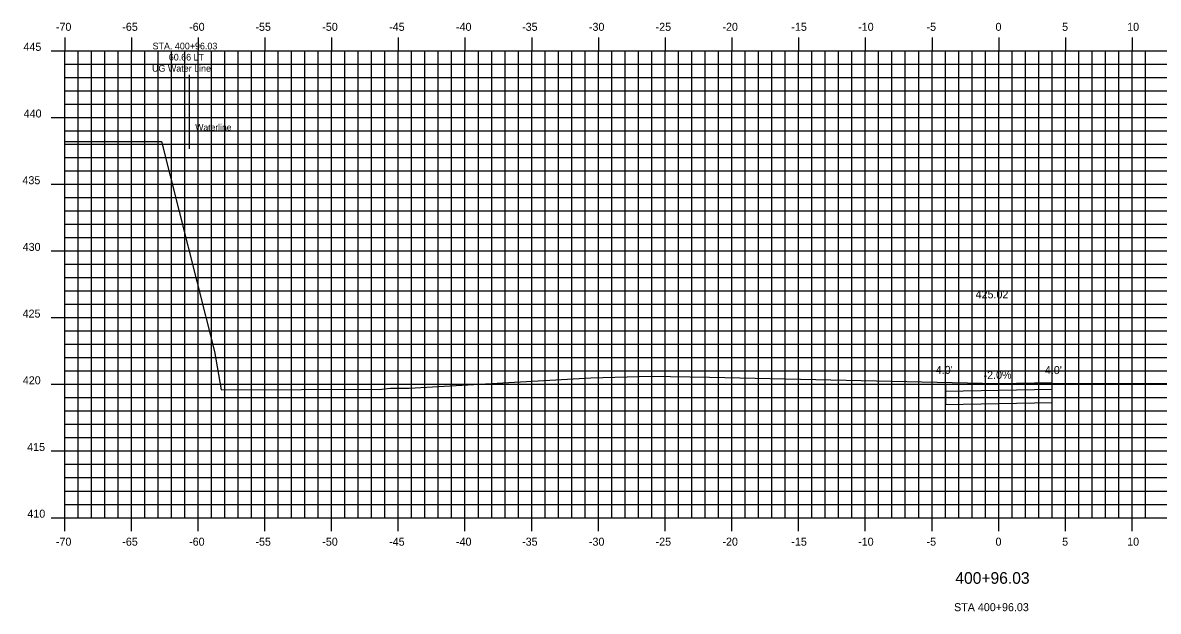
# Model space of a CAD drawing. Extents: x -161 to 764, y 111 to 210.
# Drawn here: x 606.5 to 691.6, y 165.4 to 209.6 of the extents above; entities that cross this region are included whole.
import ezdxf

# ---------------------------------------------------------------- set-up
doc = ezdxf.new("R2010")
doc.units = 0
for name, color, linetype in [('D_Property_Walkway_Paved', 7, 'Continuous'), ('D_Roadway_Centerline_Text', 7, 'Continuous'), ('D_Roadway_SubGrade', 7, 'Continuous'), ('D_Text_Monospaced', 7, 'Continuous'), ('D_Text_Standard', 7, 'Continuous'), ('H_V ANNOTATION', 7, 'Continuous'), ('MAJOR', 7, 'Continuous'), ('MINOR', 7, 'Continuous'), ('S_Roadway_Centerline', 7, 'Continuous'), ('S_Utilities_UG_Water_Line', 7, 'Continuous')]:
    doc.layers.add(name, color=color, linetype=linetype)

msp = doc.modelspace()

# ---------------------------------------------------------------- linework, layer by layer
at = {"layer": 'D_Property_Walkway_Paved'}
for p, q in [((675.653, 182.425), (675.653, 181.925)), ((683.652, 182.085), (683.652, 182.585))]:
    msp.add_line(p, q, dxfattribs=at)
for points in [[(675.653, 182.425), (683.652, 182.585)], [(675.653, 181.925), (683.652, 182.085)]]:
    msp.add_lwpolyline(points, dxfattribs=at)
at = {"layer": 'D_Roadway_SubGrade'}
msp.add_line((683.653, 181.085), (683.652, 182.085), dxfattribs=at)
msp.add_lwpolyline([(675.653, 181.925), (675.653, 180.925), (683.653, 181.085)], dxfattribs=at)
at = {"layer": 'MAJOR'}
for p, q in [((609.651, 208.447), (609.651, 207.445)), ((614.651, 208.447), (614.651, 207.445)), ((619.651, 208.447), (619.651, 207.445)), ((624.651, 208.447), (624.651, 207.445)), ((629.651, 208.447), (629.651, 207.445)), ((634.651, 208.447), (634.651, 207.445)), ((639.651, 208.447), (639.651, 207.445)), ((644.651, 208.447), (644.651, 207.445)), ((649.651, 208.447), (649.651, 207.445)), ((654.651, 208.447), (654.651, 207.445)), ((659.651, 208.447), (659.651, 207.445)), ((664.651, 208.447), (664.651, 207.445)), ((669.651, 208.447), (669.651, 207.445)), ((674.651, 208.447), (674.651, 207.445)), ((679.651, 208.447), (679.651, 207.445)), ((684.651, 208.447), (684.651, 207.445)), ((689.651, 208.447), (689.651, 207.445)), ((608.649, 207.445), (609.651, 207.445)), ((609.651, 207.445), (749.651, 207.445)), ((609.651, 172.445), (609.651, 207.445)), ((609.651, 172.445), (609.651, 207.445)), ((609.651, 207.445), (749.651, 207.445)), ((614.651, 172.445), (614.651, 207.445)), ((619.651, 172.445), (619.651, 207.445)), ((624.651, 172.445), (624.651, 207.445)), ((629.651, 172.445), (629.651, 207.445)), ((634.651, 172.445), (634.651, 207.445)), ((639.651, 172.445), (639.651, 207.445)), ((644.651, 172.445), (644.651, 207.445)), ((649.651, 172.445), (649.651, 207.445)), ((654.651, 172.445), (654.651, 207.445)), ((659.651, 172.445), (659.651, 207.445)), ((664.651, 172.445), (664.651, 207.445)), ((669.651, 172.445), (669.651, 207.445)), ((674.651, 172.445), (674.651, 207.445)), ((679.651, 172.445), (679.651, 207.445)), ((684.651, 172.445), (684.651, 207.445)), ((689.651, 172.445), (689.651, 207.445)), ((608.649, 202.445), (609.651, 202.445)), ((609.651, 202.445), (749.651, 202.445)), ((608.649, 197.445), (609.651, 197.445)), ((609.651, 197.445), (749.651, 197.445)), ((608.649, 192.445), (609.651, 192.445)), ((609.651, 192.445), (749.651, 192.445)), ((608.649, 187.445), (609.651, 187.445)), ((609.651, 187.445), (749.651, 187.445)), ((608.649, 182.445), (609.651, 182.445)), ((609.651, 182.445), (749.651, 182.445)), ((608.649, 177.445), (609.651, 177.445)), ((609.651, 177.445), (749.651, 177.445)), ((608.649, 172.445), (609.651, 172.445)), ((609.651, 172.445), (749.651, 172.445)), ((609.651, 172.445), (749.651, 172.445)), ((609.651, 171.443), (609.651, 172.445)), ((614.651, 171.443), (614.651, 172.445)), ((619.651, 171.443), (619.651, 172.445)), ((624.651, 171.443), (624.651, 172.445)), ((629.651, 171.443), (629.651, 172.445)), ((634.651, 171.443), (634.651, 172.445)), ((639.651, 171.443), (639.651, 172.445)), ((644.651, 171.443), (644.651, 172.445)), ((649.651, 171.443), (649.651, 172.445)), ((654.651, 171.443), (654.651, 172.445)), ((659.651, 171.443), (659.651, 172.445)), ((664.651, 171.443), (664.651, 172.445)), ((669.651, 171.443), (669.651, 172.445)), ((674.651, 171.443), (674.651, 172.445)), ((679.651, 171.443), (679.651, 172.445)), ((684.651, 171.443), (684.651, 172.445)), ((689.651, 171.443), (689.651, 172.445))]:
    msp.add_line(p, q, dxfattribs=at)
at = {"layer": 'MINOR'}
for p, q in [((610.651, 172.445), (610.651, 207.445)), ((611.651, 172.445), (611.651, 207.445)), ((612.651, 172.445), (612.651, 207.445)), ((613.651, 172.445), (613.651, 207.445)), ((615.651, 172.445), (615.651, 207.445)), ((616.651, 172.445), (616.651, 207.445)), ((617.651, 172.445), (617.651, 207.445)), ((618.651, 172.445), (618.651, 207.445)), ((620.651, 172.445), (620.651, 207.445)), ((621.651, 172.445), (621.651, 207.445)), ((622.651, 172.445), (622.651, 207.445)), ((623.651, 172.445), (623.651, 207.445)), ((625.651, 172.445), (625.651, 207.445)), ((626.651, 172.445), (626.651, 207.445)), ((627.651, 172.445), (627.651, 207.445)), ((628.651, 172.445), (628.651, 207.445)), ((630.651, 172.445), (630.651, 207.445)), ((631.651, 172.445), (631.651, 207.445)), ((632.651, 172.445), (632.651, 207.445)), ((633.651, 172.445), (633.651, 207.445)), ((635.651, 172.445), (635.651, 207.445)), ((636.651, 172.445), (636.651, 207.445)), ((637.651, 172.445), (637.651, 207.445)), ((638.651, 172.445), (638.651, 207.445)), ((640.651, 172.445), (640.651, 207.445)), ((641.651, 172.445), (641.651, 207.445)), ((642.651, 172.445), (642.651, 207.445)), ((643.651, 172.445), (643.651, 207.445)), ((645.651, 172.445), (645.651, 207.445)), ((646.651, 172.445), (646.651, 207.445)), ((647.651, 172.445), (647.651, 207.445)), ((648.651, 172.445), (648.651, 207.445)), ((650.651, 172.445), (650.651, 207.445)), ((651.651, 172.445), (651.651, 207.445)), ((652.651, 172.445), (652.651, 207.445)), ((653.651, 172.445), (653.651, 207.445)), ((655.651, 172.445), (655.651, 207.445)), ((656.651, 172.445), (656.651, 207.445)), ((657.651, 172.445), (657.651, 207.445)), ((658.651, 172.445), (658.651, 207.445)), ((660.651, 172.445), (660.651, 207.445)), ((661.651, 172.445), (661.651, 207.445)), ((662.651, 172.445), (662.651, 207.445)), ((663.651, 172.445), (663.651, 207.445)), ((665.651, 172.445), (665.651, 207.445)), ((666.651, 172.445), (666.651, 207.445)), ((667.651, 172.445), (667.651, 207.445)), ((668.651, 172.445), (668.651, 207.445)), ((670.651, 172.445), (670.651, 207.445)), ((671.651, 172.445), (671.651, 207.445)), ((672.651, 172.445), (672.651, 207.445)), ((673.651, 172.445), (673.651, 207.445)), ((675.651, 172.445), (675.651, 207.445)), ((676.651, 172.445), (676.651, 207.445)), ((677.651, 172.445), (677.651, 207.445)), ((678.651, 172.445), (678.651, 207.445)), ((680.651, 172.445), (680.651, 207.445)), ((681.651, 172.445), (681.651, 207.445)), ((682.651, 172.445), (682.651, 207.445)), ((683.651, 172.445), (683.651, 207.445)), ((685.651, 172.445), (685.651, 207.445)), ((686.651, 172.445), (686.651, 207.445)), ((687.651, 172.445), (687.651, 207.445)), ((688.651, 172.445), (688.651, 207.445)), ((690.651, 172.445), (690.651, 207.445)), ((609.651, 206.445), (749.651, 206.445)), ((609.651, 206.445), (610.653, 206.445)), ((609.651, 205.445), (749.651, 205.445)), ((609.651, 205.445), (610.653, 205.445)), ((609.651, 204.445), (749.651, 204.445)), ((609.651, 204.445), (610.653, 204.445)), ((609.651, 203.445), (749.651, 203.445)), ((609.651, 203.445), (610.653, 203.445)), ((609.651, 201.445), (749.651, 201.445)), ((609.651, 201.445), (610.653, 201.445)), ((609.651, 200.445), (749.651, 200.445)), ((609.651, 200.445), (610.653, 200.445)), ((609.651, 199.445), (749.651, 199.445)), ((609.651, 199.445), (610.653, 199.445)), ((609.651, 198.445), (749.651, 198.445)), ((609.651, 198.445), (610.653, 198.445)), ((609.651, 196.445), (749.651, 196.445)), ((609.651, 196.445), (610.653, 196.445)), ((609.651, 195.445), (749.651, 195.445)), ((609.651, 195.445), (610.653, 195.445)), ((609.651, 194.445), (749.651, 194.445)), ((609.651, 194.445), (610.653, 194.445)), ((609.651, 193.445), (749.651, 193.445)), ((609.651, 193.445), (610.653, 193.445)), ((609.651, 191.445), (749.651, 191.445)), ((609.651, 191.445), (610.653, 191.445)), ((609.651, 190.445), (749.651, 190.445)), ((609.651, 190.445), (610.653, 190.445)), ((609.651, 189.445), (749.651, 189.445)), ((609.651, 189.445), (610.653, 189.445)), ((609.651, 188.445), (749.651, 188.445)), ((609.651, 188.445), (610.653, 188.445)), ((609.651, 186.445), (749.651, 186.445)), ((609.651, 186.445), (610.653, 186.445)), ((609.651, 185.445), (749.651, 185.445)), ((609.651, 185.445), (610.653, 185.445)), ((609.651, 184.445), (749.651, 184.445)), ((609.651, 184.445), (610.653, 184.445)), ((609.651, 183.445), (749.651, 183.445)), ((609.651, 183.445), (610.653, 183.445)), ((609.651, 181.445), (749.651, 181.445)), ((609.651, 181.445), (610.653, 181.445)), ((609.651, 180.445), (749.651, 180.445)), ((609.651, 180.445), (610.653, 180.445)), ((609.651, 179.445), (749.651, 179.445)), ((609.651, 179.445), (610.653, 179.445)), ((609.651, 178.445), (749.651, 178.445)), ((609.651, 178.445), (610.653, 178.445)), ((609.651, 176.445), (749.651, 176.445)), ((609.651, 176.445), (610.653, 176.445)), ((609.651, 175.445), (749.651, 175.445)), ((609.651, 175.445), (610.653, 175.445)), ((609.651, 174.445), (749.651, 174.445)), ((609.651, 174.445), (610.653, 174.445)), ((609.651, 173.445), (749.651, 173.445)), ((609.651, 173.445), (610.653, 173.445))]:
    msp.add_line(p, q, dxfattribs=at)
at = {"layer": 'S_Roadway_Centerline'}
msp.add_lwpolyline([(609.651, 200.64), (616.732, 200.65), (616.804, 200.646), (616.912, 200.65), (620.887, 184.913), (621.382, 182.041), (633.421, 182.08), (634.076, 182.15), (635.455, 182.164), (649.077, 182.919), (653.611, 183.066), (657.968, 182.967), (679.594, 182.505), (693.81, 182.535), (697.869, 182.505), (720.057, 182.802), (743.82, 181.969), (746.552, 181.996), (749.651, 182.04)], dxfattribs=at)
at = {"layer": 'S_Utilities_UG_Water_Line'}
msp.add_line((618.991, 205.64), (618.991, 200.104), dxfattribs=at)

# ---------------------------------------------------------------- texts
at = {"layer": 'D_Roadway_Centerline_Text'}
for s, p in [('425.02', (677.919, 188.889)), ('STA 400+96.03', (676.305, 165.435))]:
    msp.add_text(s, height=0.6, dxfattribs=at).set_placement(p)
at = {"layer": 'D_Text_Monospaced'}
for s, height, p in [('STA. 400+96.03', 0.49998, (616.238, 207.553)), ('60.66 LT', 0.5, (617.452, 206.719)), ('UG Water Line', 0.49998, (616.196, 205.879))]:
    msp.add_text(s, height=height, dxfattribs=at).set_placement(p)
at = {"layer": 'D_Text_Standard'}
for s, p in [("-4.0'", (674.663, 183.223)), ("4.0'", (683.11, 183.21))]:
    msp.add_text(s, height=0.6, dxfattribs=at).set_placement(p)
msp.add_text('-2.0%', height=0.6, rotation=1.14576, dxfattribs=at).set_placement((678.52, 182.825))
at = {"layer": 'H_V ANNOTATION'}
for s, height, p in [('-70', 0.6, (608.993, 208.945)), ('-65', 0.6, (613.969, 208.945)), ('-60', 0.6, (618.977, 208.945)), ('-55', 0.6, (623.947, 208.945)), ('-50', 0.6, (628.955, 208.945)), ('-45', 0.6, (633.969, 208.945)), ('-40', 0.6, (638.977, 208.945)), ('-35', 0.6, (643.931, 208.945)), ('-30', 0.6, (648.939, 208.945)), ('-25', 0.6, (653.937, 208.945)), ('-20', 0.6, (658.945, 208.945)), ('-15', 0.6, (664.108, 208.945)), ('-10', 0.6, (669.116, 208.945)), ('-5', 0.6, (674.242, 208.945)), ('0', 0.6, (679.41, 208.945)), ('5', 0.6, (684.402, 208.945)), ('10', 0.6, (689.277, 208.945)), ('445', 0.6, (606.562, 207.445)), ('440', 0.6, (606.578, 202.445)), ('435', 0.6, (606.487, 197.445)), ('430', 0.6, (606.503, 192.445)), ('425', 0.6, (606.497, 187.445)), ('420', 0.6, (606.513, 182.445)), ('415', 0.6, (606.84, 177.445)), ('410', 0.6, (606.856, 172.445)), ('-70', 0.6, (608.993, 170.345)), ('-65', 0.6, (613.969, 170.345)), ('-60', 0.6, (618.977, 170.345)), ('-55', 0.6, (623.947, 170.345)), ('-50', 0.6, (628.955, 170.345)), ('-45', 0.6, (633.969, 170.345)), ('-40', 0.6, (638.977, 170.345)), ('-35', 0.6, (643.931, 170.345)), ('-30', 0.6, (648.939, 170.345)), ('-25', 0.6, (653.937, 170.345)), ('-20', 0.6, (658.945, 170.345)), ('-15', 0.6, (664.108, 170.345)), ('-10', 0.6, (669.116, 170.345)), ('-5', 0.6, (674.242, 170.345)), ('0', 0.6, (679.41, 170.345)), ('5', 0.6, (684.402, 170.345)), ('10', 0.6, (689.277, 170.345)), ('400+96.03', 0.875, (676.401, 167.488))]:
    msp.add_text(s, height=height, rotation=360, dxfattribs=at).set_placement(p)
at = {"layer": 'MAJOR'}
msp.add_text('-', height=1.5248952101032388e-17, rotation=53.1301, dxfattribs=at).set_placement((609.647, 172.445))
at = {"layer": 'S_Utilities_UG_Water_Line'}
msp.add_text('Waterline', height=0.4798, rotation=360, dxfattribs=at).set_placement((619.442, 201.469))

doc.saveas('drawing.dxf')
